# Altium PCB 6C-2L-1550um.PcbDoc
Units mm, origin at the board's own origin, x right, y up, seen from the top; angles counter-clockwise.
Board outline 9.1 x 9.6 mm, 2 copper layers (Top Layer, Bottom Layer), stack 1.586 mm thick; 1 components, 2 nets, 20 pads, 2 vias.
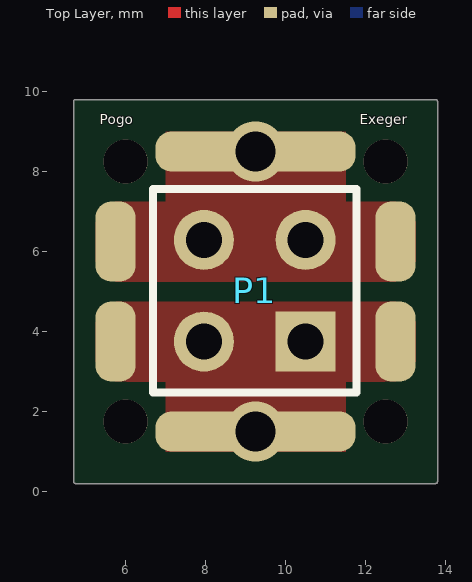
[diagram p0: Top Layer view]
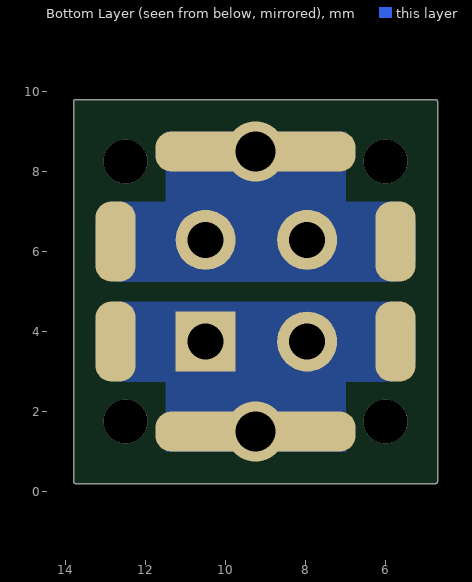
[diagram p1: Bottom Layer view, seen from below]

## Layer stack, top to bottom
Top Solder: solder mask 0.0102, Solder Resist, Dk 3.5
Top Layer: signal copper 0.018
Dielectric1: core 1.55, FR-4, Dk 4.8
Bottom Layer: signal copper 0.018
Bottom Solder: solder mask 0.0102, Solder Resist, Dk 3.5

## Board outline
4.7,0.25 4.7,9.75 cw(c4.75,9.75) 4.75,9.8 13.75,9.8 cw(c13.75,9.75) 13.8,9.75 13.8,0.25 cw(c13.75,0.25) 13.75,0.2 4.75,0.2 cw(c4.75,0.25)

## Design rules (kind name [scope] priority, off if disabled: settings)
BoardOutlineClearance [All] p1: gap=0.25 ignorepadtopadclearanceinfootprint=FALSE except(0: Arc-SplitContinuation Track-SplitContinuation SMDPad-SplitContinuation THPad-SplitContinuation Via-SplitContinuation Fill-SplitContinuation Poly-SplitContinuation Region-SplitContinuation Text-SplitContinuation)
Clearance Clearance-xPP-xTP-xTT [All] p1: gap=0.15 ignorepadtopadclearanceinfootprint=FALSE except(0: Arc-Hole Track-Hole SMDPad-Hole THPad-Hole Via-Hole Fill-Hole Poly-Hole Region-Hole Text-Hole)
ComponentClearance [All] p1: gap=0.25 collisioncheckmode=3 verticalgap=0.25 showdistances=FALSE
DiffPairsRouting [All] p1: maxlimit=0.25 minlimit=0.25 mostfreqgap=0.25 toplayer_minwidth=0.381 toplayer_maxwidth=0.381 toplayer_prefwidth=0.381 bottomlayer_minwidth=0.381 bottomlayer_maxwidth=0.381 bottomlayer_prefwidth=0.381 maxuncoupledlength=12.5
Height [All] p1: minheight=0 maxheight=25 prefheight=12.5
HoleSize HoleSize-PTH [All] p1: absolutevalues=TRUE maxlimit=2 minlimit=0.25 maxpercent=80.000 minpercent=20.000
HoleToHoleClearance [All] p1: gap=0.35 allowstackedmicrovias=TRUE
MinimumAnnularRing "Minimum IAR  >0.45mm" [((ObjectKind = 'Pad') OR (ObjectKind = 'Via')) And (Layer = 'MultiLayer') And (HoleDiameter > AsMM(0.45))] p1: minimumring=0.175 // minimum inner annular ring for pads > 0.45mm finished hole size
MinimumAnnularRing "Minimum IAR <=0.45mm" [((ObjectKind = 'Pad') OR (ObjectKind = 'Via')) And (Layer = 'MultiLayer') And (HoleDiameter <= AsMM(0.45))] p2: minimumring=0.175 // minimum inner annular ring for pads <= 0.45mm finished hole size
MinimumSolderMaskSliver [All] p1: minsoldermaskwidth=0.08
PlaneClearance PlaneClearance-IPI [All] p1: clearance=0.25
PlaneConnect [All] p1: planeconnectstyle=Relief reliefexpansion=0.175 reliefentries=4 reliefconductorwidth=0.2 reliefairgap=0.2
PolygonConnect PolygonConnect-xTW [All] p1: connectstyle=Direct reliefconductorwidth=0.2 reliefentries=4 polygonreliefangle="90 Angle" airgapwidth=0.2
RoutingCorners [All] p1: cornerstyle=45-Degree minsetback=2.5 maxsetback=2.5
RoutingVias "RoutingVias > 0.45mm" [(ObjectKind = 'Via') And (HoleDiameter > AsMM(0.45))] p1: holewidth=0.5 width=0.85 viastyle="Through Hole" minholewidth=0.5 minwidth=0.85 maxholewidth=0.9 maxwidth=1.25 // finishet hole size > 0.45mm
RoutingVias "RoutingVias <= 0.45mm" [(ObjectKind = 'Via') And (HoleDiameter <= AsMM(0.45))] p2: holewidth=0.3 width=0.65 viastyle="Through Hole" minholewidth=0.25 minwidth=0.6 maxholewidth=0.45 maxwidth=0.8 // finishet hole size <= 0.45mm
SilkToSilkClearance [All] p1: silktosilkclearance=0.2
SilkToSolderMaskClearance SilkscreenOverComponentPads [IsPad] p1: minsilkscreentomaskgap=0.2 clearancetoexposedcopper=TRUE
SolderMaskExpansion [All] p1: expansion=0 istentingtop=FALSE
UnRoutedNet [All] p1: checkbadconnections=TRUE
Width Width-xTW [All] p1: maxlimit=1.5 minlimit=0.15 preferedwidth=0.2
18 further rules are at their usual default settings.

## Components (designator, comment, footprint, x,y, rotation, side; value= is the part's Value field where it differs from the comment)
P1 "Header 2X2" HDR2X2 10.5,3.75 r90 top

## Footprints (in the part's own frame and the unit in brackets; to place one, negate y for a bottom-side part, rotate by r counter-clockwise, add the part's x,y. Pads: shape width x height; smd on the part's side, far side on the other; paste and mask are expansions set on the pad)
HDR2X2 [mm] "Connector; Header; 2x2 Position"
  rect 1.5x1.5 hole 0.9: 1(0,0)
  round 1.5 hole 0.9: 2(0,2.54) 3(2.54,0) 4(2.54,2.54)
  silkscreen extent -1.27,-1.27 3.81,3.81

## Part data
P1: "Header, 2-Pin, Dual row"

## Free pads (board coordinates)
  rrect80% 1x2 smd mask+0.05: 1(5.75,6.25) 1(12.75,6.25) 2(5.75,3.75) 2(12.75,3.75)
  rrect80% 1x2 smd far side mask+0.05: 1(5.75,6.25) 1(12.75,6.25) 2(5.75,3.75) 2(12.75,3.75)
  round 1.1 hole 1.1 unplated: 1(6,1.75) 1(6,8.25) 1(12.5,1.75) 1(12.5,8.25)
  rrect80% 5x1 smd mask+0.05: 1(9.25,8.5) 2(9.25,1.5)
  rrect80% 5x1 smd far side mask+0.05: 1(9.25,8.5) 2(9.25,1.5)

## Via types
v1: diameter 1.5, hole 1, Top Layer to Bottom Layer, 2 vias

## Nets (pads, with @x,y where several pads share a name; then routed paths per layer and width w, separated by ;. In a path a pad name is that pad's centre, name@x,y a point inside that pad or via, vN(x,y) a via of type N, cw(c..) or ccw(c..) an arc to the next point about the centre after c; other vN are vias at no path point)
N1: P1.3 P1.4 pad.1@5.75,6.25 pad.1@9.25,8.5 pad.1@12.75,6.25
  other v1: 9.25,8.5
P1: P1.1 P1.2 pad.2
  other v1: 9.25,1.5

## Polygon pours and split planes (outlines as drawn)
P1 on Top Layer "P1_L01_P012" (solid, pour order 12): 9.75,4.75 9.75,2.75 12.75,2.75 13.25,3.25 13.25,4.25 12.75,4.75
P1 on Top Layer "P1_L01_P011" (solid, pour order 11): 8.75,4.75 5.75,4.75 5.25,4.25 5.25,3.25 5.75,2.75 8.75,2.75
N1 on Top Layer "N1_L01_P009" (solid, pour order 9): 8.75,5.25 5.75,5.25 5.25,5.75 5.25,6.75 5.75,7.25 8.75,7.25
N1 on Top Layer "N1_L01_P010" (solid, pour order 10): 9.75,7.25 9.75,5.25 12.75,5.25 13.25,5.75 13.25,6.75 12.75,7.25
P1 on Top Layer "P1_L01_P002" (solid, pour order 2): 11.5,4.75 7,4.75 7,1 11.5,1
N1 on Top Layer "N1_L01_P000" (solid, pour order 0): 11.5,9 7,9 7,5.25 11.5,5.25
P1 on Bottom Layer "P1_L02_P013" (solid, pour order 13): 8.75,4.75 5.75,4.75 5.25,4.25 5.25,3.25 5.75,2.75 8.75,2.75
P1 on Bottom Layer "P1_L02_P014" (solid, pour order 14): 9.75,4.75 9.75,2.75 12.75,2.75 13.25,3.25 13.25,4.25 12.75,4.75
N1 on Bottom Layer "N1_L02_P008" (solid, pour order 8): 9.75,7.25 9.75,5.25 12.75,5.25 13.25,5.75 13.25,6.75 12.75,7.25
N1 on Bottom Layer "N1_L02_P007" (solid, pour order 7): 8.75,5.25 5.75,5.25 5.25,5.75 5.25,6.75 5.75,7.25 8.75,7.25
N1 on Bottom Layer "N1_L02_P006" (solid, pour order 6): 7,9 11.5,9 11.5,5.25 7,5.25
P1 on Bottom Layer "P1_L02_P003" (solid, pour order 3): 11.5,4.75 7,4.75 7,1 11.5,1

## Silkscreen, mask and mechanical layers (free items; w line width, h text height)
Top Overlay:
  text "Pogo" at 5.35,9.183 h0.25
  text "Exeger" at 11.85,9.183 h0.25
Dimensions:
  lines w0.1: 13.75,3.25 13.75,6.25 13.75,7.5 13.75,9.75 4.75,9.75 4.75,7.5 4.75,6.5 4.75,3.5 4.75,2.5 4.75,0.25 12.5,0.25 13.75,0.25 13.75,2.5 13.75,3.5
